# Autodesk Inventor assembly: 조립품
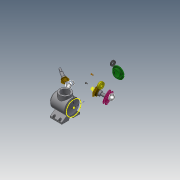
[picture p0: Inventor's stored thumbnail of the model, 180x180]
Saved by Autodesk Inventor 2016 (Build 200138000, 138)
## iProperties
Created: 2021-04
Part Number: 조립품
Document SubType Name: Assembly
Designer: user
Author: user
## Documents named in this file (17)
- C:\Users\user\Desktop\710407V1013\조립품.iam
- C:\Users\user\Desktop\710407V1013\본체.ipt
- C:\Users\user\Desktop\710407V1013\V-벨트풀리.ipt
- C:\Users\user\Desktop\710407V1013\메인 베벨기어.ipt
- C:\Users\user\Desktop\710407V1013\메인 축.ipt
- 메인 축.ipt
- C:\Users\user\Desktop\710407V1013\베어링 6203.ipt
- C:\Users\user\Desktop\710407V1013\볼트 M4 x 10.ipt
- C:\Users\user\Desktop\710407V1013\서브 베벨기어.ipt
- C:\Users\user\Desktop\710407V1013\서브 축.ipt
- 서브 축.ipt
- C:\Users\user\Desktop\710407V1013\오일실 17 x 32 x 8.ipt
- C:\Users\user\Desktop\710407V1013\와셔 4 x 16.ipt
- C:\Users\user\Desktop\710407V1013\육각볼트 M4 x 8.ipt
- C:\Users\user\Desktop\710407V1013\커버.ipt
- C:\Users\user\Desktop\710407V1013\키 4 x 4 x 14.ipt
- C:\Users\user\Desktop\710407V1013\키 5 x 5 x 14.ipt
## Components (1 placed, 1 different names)
1. V-벨트풀리:1
